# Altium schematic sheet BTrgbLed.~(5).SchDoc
size A4
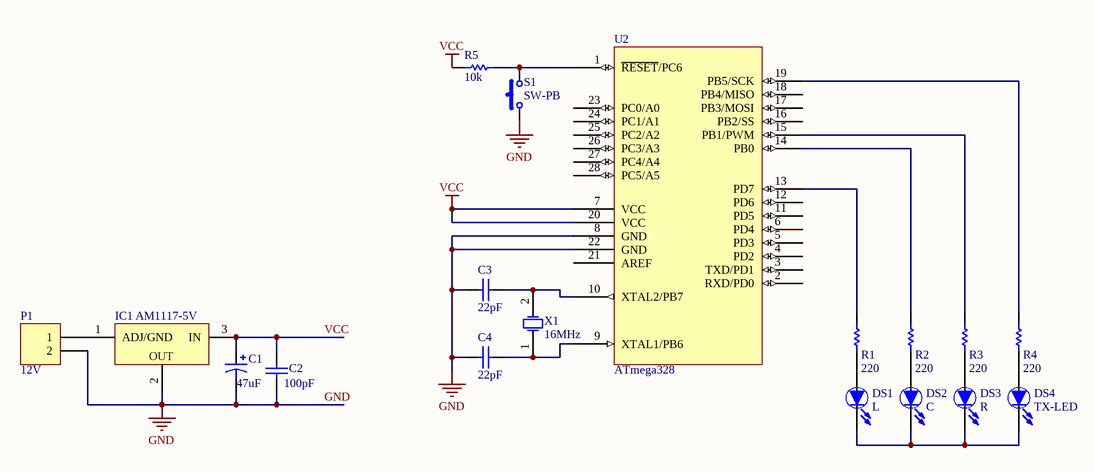
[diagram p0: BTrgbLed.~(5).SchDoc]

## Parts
C1  47uF  [RB7.6-15]
C2  value 100pF  [RAD-0.3]  (hidden comment: Cap)
C3  22pF  [C200]
C4  22pF  [C200]
DS1  L  [LED-3mm_G]
DS2  C  [LED-3mm_G]
DS3  R  [LED-3mm_G]
DS4  TX-LED  [LED-3mm_G]
IC1  AM1117-5V  [SOT-223]
P1  12V  [HDR1X2]
R1  220  [AXIAL-0.3]
R2  220  [AXIAL-0.3]
R3  220  [AXIAL-0.3]
R4  220  [AXIAL-0.3]
R5  10k  [AXIAL-0.3]
S1  SW-PB  [TACK6]
U2  ATmega328  [DIP28]
X1  16MHz  [XTAL4-8]

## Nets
GND: C1.2 C2.2 C3.1 C4.1 IC1.2(OUT) P1.2 S1.1 U2.8(GND) U2.22(GND)
VCC: C1.1 C2.1 IC1.3(IN) R5.1 U2.7(VCC) U2.20(VCC)
NetC3_2: C3.2 U2.10(XTAL2/PB7) X1.2(OSC2)
NetC4_2: C4.2 U2.9(XTAL1/PB6) X1.1(OSC1)
NetDS1_1: DS1.1(A) R1.1
NetDS1_2: DS1.2(K) DS2.2(K) DS3.2(K) DS4.2(K)
NetDS2_1: DS2.1(A) R2.1
NetDS3_1: DS3.1(A) R3.1
NetDS4_1: DS4.1(A) R4.1
NetIC1_1: IC1.1(ADJ/GND) P1.1
NetR1_2: R1.2 U2.13(PD7)
NetR2_2: R2.2 U2.14(PB0)
NetR3_2: R3.2 U2.15(PB1/PWM)
NetR4_2: R4.2 U2.19(PB5/SCK)
NetR5_2: R5.2 S1.2 U2.1(~{RESET}/PC6)

Not connected (* = marked no-connect by the designer): U2 2(RXD/PD0) 3(TXD/PD1) 4(PD2) 5(PD3) 6(PD4) 11(PD5) 12(PD6) 16(PB2/SS) 17(PB3/MOSI) 18(PB4/MISO) 21(AREF) 23(PC0/A0) 24(PC1/A1) 25(PC2/A2) 26(PC3/A3) 27(PC4/A4) 28(PC5/A5)

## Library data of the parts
C1 = Cap Pol1: Polarized Capacitor (Radial)
C2-C4 = Cap: Capacitor
DS1-DS4 = LED: Typical INFRARED GaAs LED
IC1 = AM1117
P1 = Header 2: Header, 2-Pin
R1-R5 = Res: Resistor
S1 = SW-PB: Switch
U2 = ATmega328: ATmega¨t¦C³æ´¹¤ù
X1 = XTAL: Crystal Oscillator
